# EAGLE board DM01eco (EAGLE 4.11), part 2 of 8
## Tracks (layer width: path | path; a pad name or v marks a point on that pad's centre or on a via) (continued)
-IM1  (via drill 0.61) (continued)
  Top 0.152: v356.24,75.57 356.24,69.22 347.35,60.32 347.35,57.78 D05.E2 | v346.07,222.25 346.07,226.69 353.06,233.68 v353.69,233.68 | v342.9,252.09 342.9,256.54 346.07,259.71 346.07,261.62 347.35,262.89 A05.E2
  Route2 0.152: v346.07,85.73 347.98,85.73 349.88,87.63 351.79,87.63 353.69,85.73 355.6,87.63 355.6,88.27 361.31,93.98 361.95,93.98 365.76,97.79 365.76,98.43 367.03,99.7 367.67,99.7 396.88,128.91 396.88,134.62 397.51,135.25 397.51,136.53 400.05,139.06 400.05,147.96 v403.23,151.13
  Route15 0.152: v356.24,75.57 356.24,76.2 346.71,85.73 v346.07,85.73
  Bottom 0.152: v403.23,151.13 404.5,152.4 387.35,169.55 387.35,170.81 386.71,171.45 386.71,173.36 388.62,175.26 364.49,199.39 364.49,200.03 363.22,201.3 362.58,201.3 358.77,205.11 358.77,206.38 352.43,212.72 352.43,215.9 v346.07,222.25 | v353.69,233.68 357.5,237.49 v342.9,252.09
-IM2  (via drill 0.61)
  Top 0.152: v358.77,58.42 351.79,51.43 347.98,51.43 D05.H2 | v374.65,144.78 374.65,145.41 375.92,146.69 375.92,147.96 387.35,159.39 387.35,160.02 398.14,170.81 398.78,170.81 400.05,172.09 400.05,172.72 v405.13,177.8
  Route2 0.152: v347.35,73.03 345.44,73.03 341.63,76.84 v342.9,78.11 | v334.64,90.81 334.64,92.08 346.07,103.51 346.07,109.86 374.65,138.43 v374.65,144.78
  Route15 0.152: v396.24,188.59 397.51,189.87 396.88,190.5 396.88,191.14 394.33,193.68 394.33,194.94 361.31,227.97 361.31,229.87 362.58,231.14 v361.95,231.78
  Bottom 0.152: v358.77,58.42 358.77,61.59 v347.35,73.03 | v342.9,78.11 336.55,84.46 336.55,85.09 333.38,88.27 333.38,89.54 v334.64,90.81 | v405.13,177.8 396.88,186.06 396.88,187.96 v396.24,188.59 | v361.95,231.78 361.95,232.41 360.68,233.68 360.68,234.95 346.07,249.56 346.07,255.27 347.35,256.54 A05.H2
-IM3  (via drill 0.61)
  Top 0.152: v374.65,61.59 374.65,62.23 381.63,69.22 381.63,69.85 v383.54,71.75 | v330.2,217.17 330.2,217.81 346.07,233.68 346.07,248.92 347.35,250.19 A05.K2
  Route2 0.152: v374.65,61.59 347.98,34.92 346.07,36.83 346.07,41.27 347.35,42.55 347.35,43.81 D05.K2 | v358.77,98.43 358.77,102.23 361.95,105.41 361.95,106.05 369.57,113.67 369.57,114.94 371.48,116.84 371.48,124.46 v372.11,125.09 | v330.2,184.15 330.2,183.52 332.11,181.61 336.55,186.06 336.55,189.87 335.28,191.14 343.54,199.39 343.54,201.93 342.26,203.2 344.81,205.74 344.81,208.91 333.38,220.34 v330.2,217.17
  Route15 0.152: v354.33,151.13 354.33,151.77 346.07,160.02 346.07,165.74 342.9,168.91 342.9,169.55 332.74,179.71 332.74,180.97 330.2,183.52 v330.2,184.15
  Bottom 0.152: v383.54,71.75 382.27,71.75 374.65,79.38 374.01,79.38 369.57,83.82 368.94,83.82 357.5,95.25 357.5,95.89 359.41,97.79 v358.77,98.43 | v372.11,125.09 372.11,125.73 371.48,126.37 371.48,131.44 365.12,137.8 365.12,139.06 361.95,142.24 361.95,143.51 v354.33,151.13
-IM4  (via drill 0.61)
  Top 0.152: v368.94,64.14 369.57,64.14 378.46,73.03 378.46,74.3 v387.99,83.82 | v386.08,159.39 v398.78,172.09 | v385.44,185.42 382.9,187.96 387.35,192.41 387.35,195.58 382.9,200.03 v386.71,203.84 | v354.33,247.65 353.69,247.65 351.79,245.75 348.62,245.75 347.98,245.11 A05.M2
  Route2 0.152: v368.94,64.14 368.94,62.87 351.79,45.72 351.15,45.72 346.71,41.27 347.35,40.64 347.35,38.73 D05.M2 | v368.3,110.49 367.67,111.12 370.2,113.67 370.2,114.94 372.75,117.48 372.75,118.11 374.65,120.02 374.65,123.19 373.38,124.46 384.18,135.25 384.18,140.34 v394.33,150.5
  Route15 0.152: v394.33,150.5 386.08,158.75 v386.08,159.39
  Bottom 0.152: v387.99,83.82 377.19,94.62 377.19,96.52 379.1,98.43 374.65,102.87 374.65,104.14 v368.3,110.49 | v398.78,172.09 398.14,172.09 386.71,183.52 386.71,184.15 v385.44,185.42 | v386.71,203.84 386.71,205.11 388.62,207.01 374.01,221.62 374.01,224.16 375.29,225.43 374.01,226.69 374.01,227.97 v354.33,247.65
-IM5  (via drill 0.61)
  Top 0.152: v361.95,50.16 361.95,49.53 347.98,35.56 347.98,32.38 D05.P2 | v331.47,83.82 332.11,83.82 336.55,88.27 336.55,90.81 335.28,92.08 340.36,97.16 345.44,97.16 350.52,102.23 v350.52,102.87
  Route2 0.152: v333.38,124.46 333.38,128.91 355.6,151.13 355.6,153.67 372.11,170.18 372.11,171.45 375.92,175.26 v375.92,175.9 | v355.6,195.58 355.6,198.12 370.2,212.72 370.2,220.34 371.48,221.62 371.48,229.87 366.39,234.95 361.95,230.5 359.41,230.5 353.69,236.22 352.43,236.22 349.25,239.4 347.98,238.12 A05.P2
  Bottom 0.152: v361.95,50.16 361.95,52.7 331.47,83.19 v331.47,83.82 | v350.52,102.87 349.88,102.87 335.92,116.84 335.92,119.38 337.19,120.65 v333.38,124.46 | v375.92,175.9 375.29,175.9 357.5,193.68 357.5,194.31 356.24,195.58 v355.6,195.58
-IM6  (via drill 0.61)
  Top 0.152: v393.06,78.74 387.35,73.03 387.35,68.58 341.63,22.86 343.54,20.95 345.44,20.95 347.35,22.86 347.35,24.77 D05.S2 | v392.43,87 393.06,87 403.23,97.16 403.86,97.16 v405.13,98.43 | v384.18,146.05 384.18,151.13 403.86,170.81 v403.86,171.45
  Route15 0.152: v405.13,98.43 396.88,106.68 396.88,118.75 393.06,122.56 393.06,125.09 394.97,127 387.35,134.62 387.35,135.89 384.18,139.06 v384.18,146.05 | v386.08,189.23 386.08,191.77 388.62,194.31 372.75,210.19 372.75,211.46 365.12,219.08 363.22,219.08 351.79,230.5 348.62,230.5 347.98,231.14 A05.S2
  Bottom 0.152: v393.06,78.74 393.06,86.36 v392.43,87 | v403.86,171.45 403.86,172.09 386.71,189.23 v386.08,189.23
-IM7  (via drill 0.61)
  Top 0.152: v385.44,65.41 384.81,65.41 344.81,25.4 344.81,22.86 D05.T2 | v366.39,106.05 367.67,106.05 374.65,113.03 374.65,113.67 376.56,115.57 377.19,115.57 378.46,116.84 378.46,117.48 379.73,118.75 380.37,118.75 400.05,138.43 v400.69,138.43
  Route2 0.152: v385.44,65.41 384.81,66.04 v393.7,74.93
  Route15 0.152: v386.08,170.18 386.08,172.72 388.62,175.26 371.48,192.41 371.48,198.75 346.07,224.16 346.07,226.69 344.81,227.97 A05.T2
  Bottom 0.152: v393.7,74.93 393.7,76.84 381,89.54 381,90.17 370.84,100.33 370.84,101.6 v366.39,106.05 | v400.69,138.43 400.69,149.86 375.92,174.62 379.1,177.8 383.54,173.36 383.54,172.72 v386.08,170.18
-IM8  (via drill 0.61)
  Top 0.152: v328.3,29.21 328.93,29.21 346.07,46.35 346.07,51.43 346.71,52.07 351.79,52.07 357.5,57.78 357.5,58.42 363.86,64.77 364.49,64.77 387.35,87.63 387.35,88.27 389.25,90.17 389.89,90.17 400.05,100.33 400.05,104.14 398.78,105.41 403.86,110.49 403.86,112.4 401.95,114.3 v403.23,115.57
  Route15 0.152: v392.43,135.89 392.43,136.53 389.89,139.06 389.89,142.24 372.11,160.02 372.11,160.66 371.48,161.29 371.48,173.36 364.49,180.34 364.49,181.61 369.57,186.69 368.3,187.96 368.3,188.59 358.14,198.75 358.14,200.03 353.69,204.47 353.06,204.47 351.79,205.74 351.79,212.72 353.69,214.63 349.25,219.08 347.35,219.08 344.81,221.62 A05.V2
  Bottom 0.152: v328.3,29.21 341,16.51 344.17,16.51 D05.V2 | v403.23,115.57 405.13,117.48 396.88,125.73 396.88,131.44 v392.43,135.89
-IM9  (via drill 0.61)
  Route2 0.152: v324.49,70.48 325.75,70.48 340.36,85.09 340.36,85.73 341.63,87 342.26,87 353.06,97.79 353.06,98.43 354.33,99.7 354.96,99.7 358.77,103.51 358.77,116.21 368.3,125.73 368.94,125.73 374.01,130.81 374.01,131.44 381.63,139.06 381.63,149.22 384.18,151.77 v384.18,154.94 | v372.11,189.23 372.11,189.87 384.18,201.93 v384.18,215.9
  Route15 0.152: v324.49,70.48 331.47,63.5 331.47,60.96 D06.D2 | v384.18,154.94 384.18,166.37 374.65,175.9 374.65,177.16 371.48,180.34 371.48,188.59 v372.11,189.23 | v384.18,215.9 384.18,217.17 354.96,246.38 354.33,246.38 352.43,248.28 352.43,248.92 336.55,264.8 333.38,264.8 332.11,266.06 A06.D2
-IM10  (via drill 0.61)
  Top 0.152: v217.17,96.52 217.81,96.52 222.25,100.97 222.25,103.51 220.98,104.78 229.24,113.03 v229.87,113.03
  Route2 0.152: v285.75,42.55 290.83,47.62 292.74,45.72 300.99,45.72 302.89,47.62 304.8,45.72 313.69,45.72 320.04,52.07 326.39,52.07 330.83,56.52 334.64,56.52 D06.E2 | v180.97,172.72 180.97,176.53 193.68,189.23 193.68,194.94 200.66,201.93 206.38,201.93 217.81,213.36 217.81,219.08 233.04,234.31 233.68,234.31 234.95,235.59 234.95,236.22 241.3,242.57 247.01,242.57 276.23,271.78 281.94,271.78 v295.27,285.11
  Route15 0.152: v285.75,42.55 285.75,45.09 281.94,48.89 276.23,48.89 262.89,62.23 257.81,62.23 255.27,64.77 254,64.77 247.65,71.12 242.57,71.12 227.97,85.73 227.33,85.73 217.17,95.89 v217.17,96.52 | v229.87,113.03 229.87,114.3 222.25,121.92 222.25,123.19 214,131.44 213.36,131.44 206.38,138.43 206.38,139.7 195.58,150.5 195.58,152.4 180.97,167 v180.97,172.72
  Bottom 0.152: v295.27,285.11 310.51,285.11 330.2,265.43 333.38,265.43 334.64,264.16 A06.E2
-IM11  (via drill 0.61)
  Top 0.152: v374.01,80.65 364.49,71.12 358.77,71.12 347.98,60.32 349.25,59.05 349.25,56.52 345.44,52.7 340.36,52.7 338.45,50.8 336.55,52.7 335.28,51.43 D06.H2 | v333.38,254 333.38,255.27 334.64,256.54 A06.H2
  Route2 0.152: v368.3,86.36 368.3,87.63 391.16,110.49 391.16,111.76 v391.8,112.4 | v363.22,154.31 363.22,155.58 384.18,176.53 384.18,180.34 380.37,184.15 v382.27,186.06
  Route15 0.152: v391.8,112.4 391.16,112.4 384.18,119.38 384.18,132.08 375.92,140.34 375.92,142.24 365.12,153.03 365.12,153.67 364.49,154.31 v363.22,154.31 | v382.27,186.06 382.27,187.96 377.19,193.04 377.19,194.94 379.1,196.85 367.67,208.28 364.49,208.28 363.86,208.91 362.58,208.91 358.77,212.72 358.77,215.27 358.14,215.9 358.14,218.44 346.07,230.5 346.07,236.22 342.26,240.03 341.63,240.03 340.36,241.3 340.36,242.57 333.38,249.56 v333.38,254
  Bottom 0.152: v374.01,80.65 373.38,80.65 369.57,84.46 368.94,84.46 368.3,85.09 v368.3,86.36
-INTERRUPT  (via drill 0.61)
  Top 0.152: v379.73,71.75 386.71,78.74 387.35,78.74 388.62,80.01 388.62,81.92 400.69,93.98 v401.32,93.98 | v400.05,95.89 398.14,97.79 v404.5,104.14 | v358.77,177.8 359.41,177.8 361.95,180.34 v361.95,180.97 | v354.33,191.14 v363.22,200.03 | v353.69,209.55 353.69,210.19 v359.41,215.9
  Route2 0.152: v379.73,71.75 378.46,71.75 372.11,65.41 365.76,65.41 365.12,64.77 363.86,64.77 357.5,58.42 357.5,57.78 338.45,38.73 335.28,38.73 D06.M2
  Route15 0.152: v341.63,236.22 340.36,236.22 335.92,240.66 335.92,243.21 335.28,243.84 A06.M2
  Bottom 0.152: v401.32,93.98 401.32,94.62 v400.05,95.89 | v404.5,104.14 404.5,104.78 387.99,121.29 387.35,121.29 386.08,122.56 386.08,124.46 384.18,126.37 384.18,139.7 381.63,142.24 381.63,149.86 373.38,158.12 373.38,158.75 361.31,170.81 361.31,171.45 358.77,173.99 v358.77,177.8 | v361.95,180.97 361.95,181.61 360.68,182.88 360.05,182.88 358.77,184.15 358.77,186.69 v354.33,191.14 | v363.22,200.03 v353.69,209.55 | v359.41,215.9 359.41,217.17 342.9,233.68 342.9,234.95 v341.63,236.22
-SKIP  (via drill 0.61)
  Top 0.152: v348.62,191.77 v352.43,195.58
  Route2 0.152: v316.87,53.34 316.87,55.24 332.11,70.48 333.38,70.48 344.81,81.92 346.07,81.92 346.71,82.55 351.15,82.55 356.24,87.63 356.24,88.27 361.31,93.34 361.95,93.34 365.76,97.16 367.03,97.16 368.3,98.43 368.3,99.7 383.54,114.94 v384.18,114.94 | v381,128.91 381,130.81 v385.44,135.25 | v352.43,195.58 358.77,201.93 358.77,215.27 356.87,217.17 356.87,219.71 358.77,221.62 358.77,223.52 351.15,231.14 349.88,231.14 349.25,230.5 346.07,230.5 344.17,232.41 v347.98,236.22
  Route15 0.152: v385.44,135.25 385.44,137.16 383.54,139.06 383.54,140.34 381.63,142.24 381.63,144.15 371.48,154.31 371.48,160.66 364.49,167.64 364.49,169.55 366.39,171.45 364.49,173.36 363.86,173.36 361.31,175.9 361.31,177.16 348.62,189.87 v348.62,191.77
  Bottom 0.152: v316.87,53.34 318.77,51.43 317.5,50.16 317.5,46.99 321.31,43.18 326.39,43.18 328.3,41.27 330.83,43.81 334.64,43.81 D06.K2 | v384.18,114.94 384.18,125.73 v381,128.91 | v347.98,236.22 349.88,238.12 342.9,245.11 342.9,245.75 339.09,249.56 335.92,249.56 335.28,250.19 A06.K2
ADD_ACC  (via drill 0.61)
  Top 0.152: B31.S2 17.78,162.56 17.78,165.74 26.04,173.99 26.04,176.53 26.67,177.16 B30.L2 27.3,178.44 28.57,179.71 28.57,181.61 29.84,182.88 v30.48,182.88 | v109.86,194.94 109.22,194.31 111.76,191.77 113.67,191.77 114.94,193.04 118.75,193.04 B23.E2 | v309.25,247.02 306.7,244.47 311.15,240.03 311.15,237.49 309.88,236.22 309.88,232.41 A08.S2 | v262.25,290.83 240.66,290.83 231.14,281.3 v226.69,281.3 | v184.15,256.54 184.15,255.91 148.59,220.34 143.51,220.34 127,203.84 127,201.3 128.27,200.03 121.28,193.04 v121.28,192.41
  Route2 0.152: v109.86,194.94 109.86,194.31 97.79,182.25 92.71,182.25 88.9,178.44 88.9,175.9 90.17,174.62 85.09,169.55 79.38,169.55 60.33,150.5 55.88,150.5 v50.16,144.78 | v226.69,281.3 219.07,281.3 217.81,280.03 212.09,280.03 209.55,277.5 206.38,277.5 187.32,258.44 186.06,258.44 v184.15,256.54
  Route15 0.152: B30.S2 29.84,162.56 29.84,166.37 28.57,167.64 28.57,175.9 27.3,177.16 B30.L2 | v309.25,247.02 313.06,250.83 279.4,284.48 271.78,284.48 267.97,288.29 264.8,288.29 v262.25,290.83
  Bottom 0.152: B32.H2 5.08,186.69 5.08,184.15 10.16,179.07 13.34,179.07 13.97,178.44 B31.L2 13.97,177.16 13.97,173.99 8.26,168.28 12.7,163.83 15.88,163.83 17.14,162.56 B31.S2 | 28.57,191.77 29.21,191.77 30.48,193.04 B30.E2 | 28.57,191.77 22.86,191.77 21.59,193.04 17.78,193.04 B31.E2 | v50.16,144.78 49.53,144.78 40.64,153.67 35.56,153.67 31.11,158.12 31.11,160.66 30.48,161.29 B30.S2 | v121.28,192.41 120.02,192.41 119.38,193.04 B23.E2 | 28.57,191.77 28.57,184.78 v30.48,182.88
ADD_ACC0  (via drill 0.61)
  Top 0.152: v200.66,34.92 200.66,35.56 198.12,38.1 v194.94,34.92 | v126.36,92.08 130.18,95.89 130.18,97.16 147.96,114.94 v147.96,115.57
  Route15 0.152: v200.66,34.92 201.29,34.92 205.1,31.12 206.38,31.12 207.65,29.84 207.01,29.21 208.28,27.94 208.91,27.94 213.36,23.5 214,23.5 221.62,15.88 221.62,15.24 228.6,8.26 239.4,8.26 240.03,7.62 286.38,7.62 287.65,6.35 306.07,24.77 309.25,24.77 D08.S2 | v105.41,149.86 102.87,149.86 97.79,154.94 97.79,155.58 96.52,156.84 95.89,156.84 79.38,173.36 79.38,179.07 71.12,187.33 68.58,187.33 B27.H2
  Bottom 0.152: v194.94,34.92 186.69,43.18 181.61,43.18 175.9,48.89 175.26,48.89 168.28,55.88 168.28,61.59 154.94,74.93 154.31,74.93 142.24,87 139.7,87 139.06,86.36 139.7,85.73 139.7,85.09 135.89,81.28 132.08,85.09 132.08,86.36 v126.36,92.08 | v147.96,115.57 146.05,115.57 123.19,138.43 116.84,138.43 v105.41,149.86
ADD_ACC1  (via drill 0.61)
  Top 0.152: v73.03,10.79 108.58,10.79 114.94,17.14 117.47,17.14 118.11,16.51 v117.47,15.88
  Route2 0.152: v73.03,10.79 53.98,29.84 51.44,29.84 49.53,27.94 21.59,55.88 19.05,55.88 17.78,54.61 15.88,56.52 15.88,90.17 28.57,102.87 28.57,127.64 29.21,128.27 29.21,129.54 50.8,151.13 50.8,153.03 52.7,154.94 52.7,156.21 64.77,168.28 64.77,170.81 B27.N2 | v154.94,1.27 156.84,3.18 161.93,3.18 163.19,4.45 188.59,4.45 189.87,5.71 215.9,5.71 217.17,6.99 222.88,6.99 223.52,7.62 225.43,7.62 241.3,23.5 244.47,23.5 245.75,24.77 D13.S2
  Route15 0.152: v117.47,15.88 119.38,15.88 121.28,13.97 124.46,13.97 126.36,12.07 128.27,12.07 132.08,8.26 143.51,8.26 145.41,6.35 148.59,6.35 151.76,3.18 153.03,3.18 v154.94,1.27
ADD_ACC2  (via drill 0.61)
  Top 0.152: v132.72,92.08 132.72,90.17 133.99,88.9 v128.91,83.82
  Route15 0.152: v83.19,149.22 83.19,140.97 99.06,125.09 104.14,125.09 v109.86,119.38 | v128.91,83.82 129.54,83.82 136.53,76.84 136.53,74.93 166.37,45.09 166.37,43.81 168.28,41.91 168.28,36.83 177.8,27.3 179.71,27.3 182.25,24.77 D18.S2
  Bottom 0.152: v83.19,149.22 78.74,153.67 73.66,153.67 72.39,154.94 68.58,154.94 B27.U2 | v109.86,119.38 111.12,119.38 125.09,105.41 125.73,105.41 128.91,102.23 128.91,100.33 133.35,95.89 133.35,92.71 v132.72,92.08
ADD_ACC3  (via drill 0.61)
  Route2 0.152: v18.41,130.81 24.13,136.53 21.59,139.06 21.59,142.88 31.75,153.03 31.75,154.31 41.27,163.83 41.27,169.55 48.26,176.53 48.26,177.8 49.53,179.07 50.16,179.07 55.24,184.15 55.24,186.69 B28.H2
  Route15 0.152: v18.41,130.81 18.41,128.91 79.38,67.95 79.38,56.52 80.01,55.88 85.09,55.88 111.12,29.84 112.39,29.84 114.94,27.3 116.84,27.3 118.75,25.4 D23.S2
ADD_ACC4  (via drill 0.61)
  Top 0.152: v67.94,34.92 59.05,26.04 55.88,26.04 D28.S2 | v4.45,104.78 38.73,139.06 38.73,140.97 v53.98,156.21
  Bottom 0.152: v67.94,34.92 67.94,36.2 66.67,37.47 66.67,42.55 v4.45,104.78 | v53.98,156.21 53.98,169.55 52.7,170.81 B28.N2
ADD_ACC5  (via drill 0.61)
  Top 0.152: v76.83,200.66 74.93,202.56 92.08,219.71 97.16,219.71 104.78,227.33 104.78,229.87 106.05,231.14 A24.S2
  Route2 0.152: v45.72,169.55 46.99,169.55 71.12,193.68 71.75,193.04 73.03,194.31 73.03,195.58 76.83,199.39 v76.83,200.66
  Bottom 0.152: v45.72,169.55 45.72,168.91 52.07,162.56 50.8,161.29 50.8,158.12 53.98,154.94 55.24,154.94 B28.U2
ADD_ACC6
  Route15 0.152: B29.H2 42.55,187.96 42.55,191.77 41.27,193.04 41.27,197.49 40.64,198.12 40.64,199.39 34.29,205.74 34.29,219.08 40.64,225.43 38.1,227.97 38.1,229.24 41.91,233.05 42.55,232.41 A29.S2
B32M  (via drill 0.61)
  Top 0.152: PDP-12/8I/8.2 12.06,286.38 10.79,286.38 PDP-12/8I/8.4 9.53,286.38 8.26,286.38 PDP-12/8I/8.6 7.62,285.75 3.17,281.3 3.17,221.62 1.91,220.34 v1.91,215.27
  Route15 0.152: v1.91,215.27 2.54,214.63 2.54,205.11 7.62,200.03 2.54,194.94 2.54,192.41 3.17,191.77 3.17,180.34 4.45,179.07 4.45,175.26 B32.M2
B_ENABLE0  (via drill 0.61)
  Top 0.152: v347.98,183.52 347.98,184.15 353.69,189.87 354.33,189.87 356.24,191.77 358.77,191.77 360.05,193.04 B04.E2 | v231.14,282.57 227.97,285.75 214,271.78 213.36,271.78 v206.38,264.8 | v338.45,200.66 335.28,197.49 335.28,194.31 B06.E2
  Route2 0.152: A20.S2 157.48,232.41 160.66,232.41 183.51,255.27 184.15,255.27 184.78,255.91 186.69,255.91 189.23,253.37 196.85,260.99 196.85,261.62 200.66,265.43 203.84,265.43 204.47,266.06 A16.D2
  Route15 0.152: v338.45,200.66 337.82,200.66 333.38,205.11 333.38,207.01 332.11,208.28 330.83,208.28 325.12,214 323.85,214 323.21,214.63 318.77,214.63 314.32,219.08 v313.06,219.08
  Bottom 0.152: B14.T2 229.87,159.39 229.87,162.56 218.44,173.99 218.44,174.62 214,179.07 213.36,179.07 193.68,198.75 193.68,204.47 189.87,208.28 187.96,208.28 182.88,213.36 179.07,213.36 168.91,223.52 168.28,223.52 161.29,230.5 158.12,230.5 157.48,231.14 A20.S2 | v347.98,183.52 338.45,193.04 335.28,193.04 B06.E2 | v231.14,282.57 233.04,280.67 237.49,280.67 239.4,278.76 241.3,278.76 242.57,277.5 247.65,277.5 258.44,266.7 258.44,264.16 A12.E2 259.08,262.89 259.71,262.25 259.71,259.71 267.33,252.09 273.05,252.09 277.5,247.65 278.76,247.65 283.21,243.21 288.29,243.21 312.42,219.08 v313.06,219.08 | v206.38,264.8 205.1,266.06 A16.D2
B_ENABLE1  (via drill 0.61)
  Top 0.152: 340.36,189.23 346.07,194.94 v350.52,194.94 | 340.36,189.23 332.11,180.97 332.11,178.44 B06.L2 | v247.65,250.83 248.28,251.46 250.19,251.46 251.46,252.73 256.54,252.73 258.44,254.64 258.44,256.54 A12.H2 | v216.53,257.81 216.53,256.54 212.09,252.09 208.91,252.09 208.28,251.46 A16.K2 | v341,189.23 340.36,189.23
  Route2 0.152: v191.13,269.24 168.28,246.38 162.56,246.38 157.48,241.3 157.48,238.76 A20.P2
  Route15 0.152: v350.52,194.94 350.52,193.68 354.33,189.87 355.6,189.87 356.24,189.23 358.77,189.23 360.05,187.96 B04.H2 | v191.13,269.24 191.77,269.88 206.38,255.27 206.38,252.73 207.65,251.46 A16.K2 | v197.49,168.91 204.47,161.93 204.47,159.39 B16.T2 | v179.71,194.94 182.25,197.49 173.99,205.74 173.99,214.63 172.09,216.53 172.09,217.81 170.81,219.08 170.81,221.62 158.12,234.31 158.12,236.86 157.48,237.49 A20.P2 | v247.65,250.83 247.65,252.09 240.66,259.08 238.12,259.08 224.16,245.11 223.52,245.75 222.88,245.75 222.25,246.38 221.62,246.38 220.34,247.65 223.52,250.83 v216.53,257.81 | v341,189.23 341,191.14 333.38,198.75 333.38,203.84 330.2,207.01 330.2,207.65 329.56,208.28 325.12,208.28 321.31,212.09 317.5,208.28 v311.79,208.28 | v274.32,245.75 273.05,245.75 262.89,255.91 259.71,255.91 259.08,256.54 A12.H2
  Bottom 0.152: v197.49,168.91 196.85,168.91 194.94,170.81 194.94,172.72 188.59,179.07 187.96,179.07 180.97,186.06 180.97,193.68 v179.71,194.94 | v311.79,208.28 311.15,208.28 281.31,238.12 281.31,238.76 277.5,242.57 276.86,242.57 274.32,245.11 v274.32,245.75
B_ENABLE2  (via drill 0.61)
  Top 0.152: v189.23,170.18 189.23,170.81 188.59,171.45 224.79,207.65 v225.43,207.65 | v178.44,225.43 182.25,221.62 187.96,227.33 193.68,227.33 198.75,232.41 199.39,232.41 200.66,233.68 203.84,233.68 204.47,234.31 A16.R2 | v248.28,258.44 244.47,258.44 v211.46,225.43 | v300.36,150.5 297.81,150.5 v289.56,142.24 | v254,171.45 252.73,171.45 245.11,163.83 244.47,163.83 231.78,151.13 229.24,151.13 226.06,147.96 v223.52,147.96
  Route2 0.152: B04.K2 360.05,180.34 360.05,177.8 348.62,166.37 342.9,166.37 339.09,162.56 335.28,162.56 B06.S2 334.64,161.29 334.64,158.75 326.39,150.5 324.49,150.5 v315.6,141.61 | v194.94,163.83 192.41,161.29 192.41,159.39 B17.T2 | v223.52,147.96 218.44,142.88 214.63,142.88 v210.19,138.43
  Route15 0.152: v248.28,258.44 251.46,255.27 252.09,255.27 255.91,251.46 258.44,251.46 A12.K2
  Bottom 0.152: v194.94,163.83 194.94,165.1 189.87,170.18 v189.23,170.18 | v225.43,207.65 225.43,209.55 224.16,210.82 224.16,212.72 v211.46,225.43 206.38,230.5 206.38,233.05 205.1,234.31 A16.R2 | v178.44,225.43 178.44,226.06 160.66,243.84 157.48,243.84 A20.M2 | v315.6,141.61 310.51,141.61 309.25,142.88 307.98,142.88 v300.36,150.5 | v289.56,142.24 288.29,142.24 276.23,154.31 270.51,154.31 269.88,154.94 269.88,159.39 269.24,160.02 264.16,160.02 257.81,166.37 257.81,167 254,170.81 v254,171.45 | v210.19,138.43 207.01,138.43 205.1,140.34 205.1,140.97 200.03,146.05 200.03,147.32 195.58,151.77 195.58,153.67 197.49,155.58 196.22,156.84 193.68,156.84 192.41,158.12 B17.T2
B_ENABLE3  (via drill 0.61)
  Top 0.152: v166.37,245.11 167,245.11 189.87,267.97 191.13,267.97 191.77,267.33 A17.D2 | 238.76,227.33 254,242.57 257.18,242.57 258.44,243.84 A12.M2 | 238.76,227.33 205.74,194.31 205.1,194.31 185.42,174.62 187.96,172.09 187.96,170.81 186.69,169.55 186.69,168.28 185.42,167 184.78,167 179.71,161.93 179.71,159.39 B18.T2 | 238.76,227.33 v239.4,227.33
  Route2 0.152: v340.36,158.75 341,158.75 343.54,161.29 343.54,162.56 344.81,163.83 346.71,163.83 355.6,172.72 358.77,172.72 360.05,173.99 B04.M2 | v305.44,186.69 306.07,187.33 304.8,188.59 304.8,191.77 306.7,193.68 309.25,193.68 B08.E2
  Route15 0.152: v340.36,158.75 340.36,159.39 307.98,191.77 309.25,193.04 B08.E2 | v305.44,186.69 303.53,184.78 302.89,185.42 302.26,185.42 295.27,192.41 295.27,198.75 287.02,207.01 287.02,219.08 275.59,230.5 269.88,230.5 259.71,240.66 259.71,243.21 259.08,243.84 A12.M2
  Bottom 0.152: v166.37,245.11 156.84,254.64 155.57,253.37 156.84,252.09 156.84,251.46 A20.K2 | v239.4,227.33 238.76,227.97 238.76,229.24 206.38,261.62 200.66,261.62 196.22,266.06 192.41,266.06 A17.D2
B_ENABLE4  (via drill 0.61)
  Top 0.152: v193.04,186.69 191.77,185.42 190.5,185.42 184.15,179.07 184.15,178.44 176.53,170.81 175.9,170.81 167,161.93 167,159.39 B19.T2 | v173.35,216.53 173.35,219.08 167,225.43 v179.07,237.49 190.5,248.92 193.68,248.92 194.94,250.19 A17.K2 | 327.02,195.58 309.88,178.44 306.7,178.44 B08.L2 | 327.02,195.58 329.56,195.58 v330.2,196.22 | v264.8,246.38 264.16,246.38 260.35,242.57 260.35,241.94 259.08,240.66 259.08,238.76 A12.P2 | v323.85,198.75 326.39,198.75 328.3,196.85 327.02,195.58 | v208.91,240.03 208.91,241.94 215.9,248.92 220.34,248.92 v221.62,247.65
  Route15 0.152: v193.04,186.69 186.69,193.04 186.69,194.31 189.23,196.85 180.97,205.11 180.97,208.91 v173.35,216.53 | v342.9,183.52 349.25,177.16 349.25,176.53 355.6,170.18 358.77,170.18 360.05,168.91 B04.P2 | v264.8,246.38 266.7,246.38 276.86,236.22 282.57,236.22 314.32,204.47 315.6,204.47 321.31,198.75 v323.85,198.75 | v221.62,247.65 221.62,248.28 231.14,257.81 v230.5,258.44
  Bottom 0.152: v179.07,237.49 179.07,238.12 160.66,256.54 157.48,256.54 A20.H2 | v330.2,196.22 330.2,195.58 342.26,183.52 v342.9,183.52 | v208.91,240.03 198.75,250.19 195.58,250.19 A17.K2 | v230.5,258.44 234.95,258.44 250.82,242.57 256.54,242.57 257.18,241.94 257.18,240.03 258.44,238.76 A12.P2
B_ENABLE5  (via drill 0.61)
  Top 0.152: v330.2,185.42 328.93,184.15 | 328.93,184.15 309.88,165.1 309.88,162.56 B08.S2 | v195.58,227.97 193.68,226.06 193.68,225.43 192.41,224.16 191.77,224.16 177.16,209.55 184.15,202.56 184.15,199.39 180.97,196.22 180.97,189.23 164.47,172.72 163.83,172.72 162.56,171.45 162.56,170.81 154.31,162.56 154.31,159.39 B20.T2 | v217.81,205.11 221.62,205.11 225.43,208.91 226.06,208.91 243.84,226.69 250.19,226.69 254.63,231.14 258.44,231.14 A12.S2 | 328.93,184.15 325.75,187.33 330.2,191.77 330.2,193.04 336.55,199.39 336.55,200.66 334.01,203.2 332.74,201.93 330.83,201.93 328.93,203.84 330.83,205.74 330.83,211.46 v331.47,212.09 | v278.76,248.92 276.86,248.92 274.95,250.83 269.88,245.75 v269.88,238.76
  Route2 0.152: v269.88,238.76 269.24,238.76 262.89,232.41 262.89,230.5 264.8,228.6 262.89,226.69 260.99,226.69 257.81,229.87 259.08,231.14 A12.S2
  Route15 0.152: v330.2,185.42 334.01,185.42 355.6,163.83 358.77,163.83 360.05,162.56 B04.S2 | A20.E2 157.48,262.89 160.66,262.89 184.15,239.4 185.42,239.4 187.32,237.49 187.32,236.86 187.96,236.22 191.13,236.22 191.77,235.59 A17.R2 | v331.47,212.09 330.2,212.09 327.02,215.27 327.02,216.53 320.04,223.52 314.32,223.52 313.69,224.16 307.34,224.16 300.99,230.5 295.27,230.5 282.57,243.21 282.57,248.28 281.94,248.92 v278.76,248.92
  Bottom 0.152: A17.R2 192.41,234.31 193.68,233.05 193.68,231.14 195.58,229.24 v195.58,227.97 203.2,220.34 207.01,220.34 208.91,218.44 206.38,215.9 206.38,212.72 210.82,208.28 215.26,208.28 217.81,205.74 v217.81,205.11
B_ENABLE6  (via drill 0.61)
  Top 0.152: B23.S2 119.38,162.56 119.38,165.1 124.46,170.18 125.73,170.18 v127,171.45 127,172.09 v132.72,177.8 | A18.D2 179.07,266.06 178.44,265.43 178.44,262.89 172.72,257.18 170.81,259.08 v169.54,259.08 168.91,259.08 146.05,236.22 146.05,235.59 137.79,227.33 137.16,227.33 124.46,214.63 120.02,214.63 115.57,210.19 115.57,207.65 120.65,202.56 120.65,199.39 115.57,194.31 v114.94,194.31 | v220.34,246.38 v214.63,246.38 | v299.08,251.46 296.55,254 275.59,233.05 273.69,233.05 v273.05,232.41 | v269.88,235.59 268.61,236.86 267.97,236.22 267.33,236.22 266.7,235.59 266.7,233.05 267.97,231.78 262.89,226.69 259.71,226.69 259.08,226.06 A12.U2
  Route15 0.152: v169.54,259.08 165.1,259.08 158.12,266.06 154.31,266.06 A20.D2 | v220.34,246.38 220.98,245.75 222.25,245.75 231.14,236.86 237.49,236.86 241.3,233.05 247.01,233.05 248.28,231.78 249.56,231.78 255.27,226.06 258.44,226.06 A12.U2 | v214.63,246.38 214.63,247.02 212.09,249.56 203.84,249.56 201.93,247.65 183.51,266.06 179.71,266.06 A18.D2 | v368.3,153.03 367.67,153.67 365.76,153.67 363.86,155.58 360.68,155.58 B04.U2 | v369.57,156.84 368.3,158.12 368.3,160.66 369.57,161.93 361.95,169.55 361.95,170.81 355.6,177.16 355.6,179.71 356.87,180.97 347.98,189.87 347.98,191.14 346.07,193.04 346.07,194.94 350.52,199.39 347.98,201.93 347.98,203.2 314.32,236.86 313.69,236.86 v299.08,251.46
  Bottom 0.152: v127,171.45 127,170.18 137.16,160.02 140.34,160.02 140.97,159.39 B21.T2 | v368.3,153.03 370.84,155.58 v369.57,156.84 | v273.05,232.41 v269.88,235.59 | v132.72,177.8 131.44,177.8 v114.94,194.31
BMPX0  (via drill 0.61)
  Top 0.152: v323.21,48.26 309.88,34.92 309.88,32.38 D08.P2 | v302.89,73.66 v307.34,78.11 | v267.33,127.64 268.61,127.64 v283.85,142.88 | v277.5,151.77 277.5,152.4 295.27,170.18 295.27,172.72 296.55,173.99 B09.M2
  Bottom 0.152: v323.21,48.26 325.75,50.8 v302.89,73.66 | v307.34,78.11 307.34,80.65 301.62,86.36 301.62,87 271.14,117.48 270.51,117.48 269.24,118.75 269.24,122.56 270.51,123.83 267.33,127 v267.33,127.64 | v283.85,142.88 283.85,144.15 280.67,147.32 280.67,148.59 v277.5,151.77 | B10.D2 281.31,196.22 281.31,193.04 292.74,181.61 292.74,179.07 291.46,177.8 292.74,176.53 294.64,176.53 296.55,174.62 B09.M2
BMPX1  (via drill 0.61)
  Top 0.152: v287.02,69.85 249.56,32.38 246.38,32.38 D13.P2 | v242.57,113.67 242.57,114.3 257.18,128.91 257.18,129.54 262.25,134.62 262.89,134.62 278.76,150.5 278.76,153.03 295.91,170.18 295.91,171.45 298.45,173.99 298.45,175.9 297.18,177.16 295.27,175.26 295.27,173.36 294,172.09 B09.N2
  Route15 0.152: B10.F2 281.31,189.87 281.31,186.06 284.48,182.88 285.75,182.88 299.72,168.91 299.72,168.28 297.18,165.74 295.27,167.64 295.27,169.55 294,170.81 B09.N2
  Bottom 0.152: v287.02,69.85 259.71,97.16 259.08,97.16 254,102.23 254,102.87 246.38,110.49 245.75,110.49 v242.57,113.67
BMPX2  (via drill 0.61)
  Top 0.152: v307.34,155.58 304.8,153.03 304.8,152.4 292.74,140.34 292.74,139.06 261.62,107.95 260.99,107.95 257.81,104.78 257.81,104.14 253.37,99.7 252.73,99.7 251.46,98.43 251.46,97.79 240.66,87 240.03,87 238.76,85.73 238.76,85.09 186.06,32.38 182.88,32.38 D18.P2
  Route15 0.152: B10.J2 281.31,183.52 282.57,183.52 283.85,182.25 285.75,182.25 295.27,172.72 295.27,170.18 296.55,168.91 B09.P2
  Bottom 0.152: v307.34,155.58 306.7,155.58 297.81,164.47 297.81,167 297.18,167.64 B09.P2
BMPX3  (via drill 0.61)
  Top 0.152: v274.32,180.97 242.57,149.22 241.3,149.22 233.04,140.97 231.78,140.97 215.9,125.09 214.63,125.09 213.36,123.83 213.36,123.19 189.87,99.7 189.23,99.7 187.96,98.43 187.96,97.79 122.56,32.38 119.38,32.38 D23.P2 | v290.83,163.83 291.46,164.47 293.37,164.47 B09.R2
  Bottom 0.152: v274.32,180.97 279.4,175.9 | 279.4,175.9 280.67,177.16 B10.L2 | v290.83,163.83 290.83,164.47 279.4,175.9
BMPX4  (via drill 0.61)
  Top 0.152: v99.69,73.03 59.05,32.38 55.88,32.38 D28.P2 | v132.72,41.27 132.72,41.91 162.56,71.75 165.1,71.75 175.9,82.55 178.44,82.55 186.06,90.17 186.69,90.17 213.36,116.84 213.36,117.48 214.63,118.75 215.26,118.75 v229.24,132.72 | v233.04,129.54 244.47,140.97 247.65,140.97 276.86,170.18 280.04,170.18 280.67,170.81 B10.N2
  Route2 0.152: B09.S2 296.55,161.29 294.64,161.29 294,160.66 292.1,160.66 291.46,160.02 289.56,160.02 281.31,168.28 281.31,170.81 B10.N2
  Route15 0.152: v229.24,132.72 229.87,132.72 v233.04,129.54
  Bottom 0.152: v99.69,73.03 123.83,48.89 125.09,48.89 v132.72,41.27
BMPX5  (via drill 0.61)
  Route2 0.152: B09.T2 293.37,159.39 289.56,159.39 282.57,166.37 281.31,165.1 B10.R2 280.67,164.47 280.04,163.83 276.23,163.83 272.42,160.02 266.7,160.02 251.46,144.78 248.92,147.32 248.92,147.96 252.09,151.13 252.09,151.77 255.27,154.94 254,156.21 v254,158.75 | v137.79,278.13 137.16,278.13 120.65,261.62 120.65,260.99 117.47,257.81 117.47,252.73 106.68,241.94 106.68,238.76 A24.P2
  Route15 0.152: v137.79,278.13 139.7,278.13 165.1,252.73 165.1,251.46 168.28,248.28 168.28,243.21 187.96,223.52 193.04,223.52 198.75,217.81 200.03,217.81 231.78,186.06 237.49,186.06 238.76,184.78 238.76,183.52 236.22,180.97 254.63,162.56 254.63,160.66 253.37,159.39 v254,158.75
BMPX6  (via drill 0.61)
  Top 0.152: v81.92,274.32 46.35,238.76 43.18,238.76 A29.P2 | v210.19,219.08 v220.98,219.08
  Bottom 0.152: v81.92,274.32 98.42,290.83 122.56,290.83 123.83,289.56 135.25,289.56 140.97,283.84 146.05,283.84 210.19,219.71 v210.19,219.08 | v220.98,219.08 227.97,219.08 231.14,215.9 233.04,215.9 244.47,204.47 244.47,198.12 280.04,162.56 | 280.04,162.56 280.04,160.02 280.67,159.39 B10.T2 | 280.04,162.56 289.56,153.03 293.37,153.03 B09.V2
BREAK  (via drill 0.61)
  Top 0.152: 306.07,179.07 307.98,179.07 309.25,180.34 B08.K2 | 306.07,179.07 305.44,179.07 304.17,177.8 307.98,173.99 307.98,170.81 306.7,169.55 306.7,165.74 B08.R2 | 306.07,179.07 306.7,179.71 304.8,181.61 304.8,184.78 309.88,189.87 v309.88,191.77 311.79,193.68 310.51,194.94 310.51,197.49 v328.3,215.27 | v308.61,233.68 309.25,234.31 309.25,237.49 A08.P2 | 327.02,176.53 332.74,176.53 334.64,178.44 334.64,180.34 B06.K2 | v319.4,168.91 327.02,176.53 | v338.45,188.59 338.45,187.96 327.02,176.53 | v109.86,173.99 109.86,174.62 142.88,207.65 144.15,207.65 149.22,212.72 149.22,220.34 177.8,248.92 180.97,248.92 182.25,250.19 A18.K2 182.88,251.46 183.51,252.09 183.51,254.64 191.13,262.25 196.22,262.25 198.12,264.16 199.39,264.16 200.66,265.43 201.29,265.43 209.55,273.69 209.55,277.5 v215.9,283.84
  Route2 0.152: v327.66,160.02 329.56,160.02 331.47,161.93 331.47,164.47 B06.R2
  Route15 0.152: v338.45,188.59 337.19,188.59 332.11,193.68 332.11,196.22 B06.D2 | v109.86,173.99 115.57,168.28 115.57,165.74 B23.R2 | v308.61,233.68 304.17,233.68 300.99,236.86 295.27,236.86 263.52,268.6 256.54,268.6 247.65,277.5 246.38,277.5 239.4,284.48 216.53,284.48 v215.9,283.84
  Bottom 0.152: 318.77,168.91 310.51,177.16 310.51,179.71 309.88,180.34 B08.K2 | 318.77,168.91 v327.66,160.02 | v309.88,191.77 309.25,191.77 306.7,194.31 306.7,196.22 B08.D2 | v308.61,233.68 310.51,233.68 328.3,215.9 v328.3,215.27 | 318.77,168.91 v319.4,168.91 | A19.D2 167,266.06 170.18,266.06 180.97,255.27 180.97,252.73 182.25,251.46 A18.K2
BREAK\  (via drill 0.61)
  Top 0.152: v360.05,171.45 v334.64,146.05 | v220.98,266.06 217.17,269.88 186.69,239.4 183.51,239.4 182.88,238.76 A18.P2
  Route2 0.152: v374.65,155.58 375.29,156.21 373.38,158.12 373.38,161.29 B03.S2
  Bottom 0.152: v374.65,155.58 374.65,156.21 368.3,162.56 368.3,163.19 v360.05,171.45 | v334.64,146.05 278.76,201.93 276.86,201.93 274.95,200.03 272.42,202.56 272.42,205.11 273.69,206.38 273.05,207.01 273.05,214 v220.98,266.06 | A18.N2 179.71,240.66 180.34,240.66 182.25,238.76 A18.P2
BRK_REQ  (via drill 0.61)
  Top 0.152: v240.03,282.57 249.56,282.57 v255.91,288.92
  Route2 0.152: v192.41,290.19 190.5,288.29 173.99,288.29 173.35,287.65 158.75,287.65 158.12,287.02 156.84,287.02 153.03,290.83 140.97,290.83 139.06,288.92 129.54,288.92 121.92,281.3 113.67,281.3 113.03,280.67 99.69,280.67 96.52,277.5 92.71,277.5 87,271.78 85.72,271.78 72.39,258.44 66.67,258.44 31.75,223.52 26.04,223.52 13.34,210.82 13.34,205.74 5.08,197.49 1.91,197.49 B32.D2
  Route15 0.152: v192.41,290.19 193.68,288.92 201.93,288.92 203.2,287.65 206.38,287.65 212.72,281.3 216.53,281.3 219.07,283.84 238.76,283.84 v240.03,282.57 | v255.91,288.92 263.52,288.92 264.8,287.65 267.97,287.65 271.78,283.84 279.4,283.84 307.98,255.27 307.98,252.73 309.25,251.46 A08.K2
BRK_REQ0  (via drill 0.61)
  Top 0.152: 231.78,178.44 233.68,178.44 238.76,183.52 238.76,184.15 240.03,185.42 241.3,185.42 244.47,188.59 250.19,188.59 254,192.41 255.91,192.41 v256.54,193.04 | 231.78,178.44 230.5,178.44 B14.L2 | v150.5,208.28 149.22,208.28 122.56,181.61 119.38,181.61 B23.K2 | v163.19,203.2 164.47,203.2 172.09,210.82 173.99,210.82 v181.61,218.44 | 231.78,178.44 v231.78,182.88 | v354.33,217.17 351.15,217.17 347.35,220.98 v337.82,211.46 | v304.17,196.85 302.89,196.85 300.99,194.94 295.27,194.94 294,196.22 B09.D2
  Route2 0.152: v271.14,179.07 273.05,179.07 273.69,179.71 274.32,179.71 275.59,180.97 275.59,182.25 290.19,196.85 293.37,196.85 B09.D2 | v205.1,144.15 206.38,144.15 215.9,153.67 215.9,154.94 222.25,161.29 222.25,163.83 220.98,165.1 226.06,170.18 231.14,170.18 231.78,170.81 231.78,175.9 230.5,177.16 B14.L2 | v329.56,219.08 329.56,218.44 323.85,212.72 323.85,211.46 313.69,201.3 308.61,201.3 v304.17,196.85
  Route15 0.152: v181.61,218.44 181.61,217.81 194.31,205.11 199.39,205.11 203.2,201.3 204.47,201.3 207.01,198.75 212.09,198.75 224.16,186.69 224.79,186.69 228.6,182.88 v231.78,182.88
  Bottom 0.152: v256.54,193.04 260.99,188.59 261.62,188.59 263.52,186.69 263.52,186.06 264.16,185.42 269.24,185.42 269.88,184.78 269.88,180.34 v271.14,179.07 | v150.5,208.28 151.76,208.28 158.75,201.3 161.29,201.3 v163.19,203.2 | v205.1,144.15 205.74,144.15 211.46,138.43 212.72,138.43 226.06,125.09 226.06,123.83 227.33,122.56 227.97,122.56 250.82,99.7 250.82,99.06 252.73,97.16 253.37,97.16 305.44,45.09 309.25,45.09 D08.K2 | v354.33,217.17 362.58,208.91 368.3,208.91 369.57,207.65 369.57,207.01 382.27,194.31 385.44,194.31 B02.E2 | v337.82,211.46 337.19,211.46 v329.56,219.08
BRK_REQ1  (via drill 0.61)
  Top 0.152: v131.44,163.83 131.44,165.1 v133.35,167 | v254,149.22 247.65,149.22 243.21,144.78 241.3,144.78 v237.49,140.97 | v375.29,194.31 375.29,193.68 368.3,186.69 368.3,186.06 358.14,175.9 358.14,174.62 v357.5,173.99 | v325.12,192.41 324.49,192.41 312.42,180.34 v312.42,179.71
  Route2 0.152: v155.57,144.15 174.62,144.15 175.9,145.41 175.9,151.77 192.41,168.28 | 192.41,168.28 200.66,176.53 203.84,176.53 204.47,177.16 B16.L2 | v249.56,50.8 246.38,47.62 246.38,45.09 D13.K2 | v184.15,121.29 184.15,123.19 182.88,124.46 196.85,138.43 196.85,140.97 200.66,144.78 201.29,144.78 206.38,149.86 206.38,154.31 192.41,168.28 | v254,149.22 255.91,151.13 257.18,151.13 294.64,188.59 295.91,188.59 297.18,189.87 297.18,193.04 B09.E2
  Route15 0.152: v357.5,173.99 349.25,182.25 347.98,182.25 346.07,184.15 346.07,184.78 345.44,185.42 339.73,185.42 339.09,186.06 333.38,186.06 329.56,189.87 328.93,189.87 326.39,192.41 v325.12,192.41
  Bottom 0.152: v131.44,163.83 127,163.83 116.2,174.62 116.2,177.16 B23.L2 | v133.35,167 134.62,168.28 149.86,153.03 149.86,149.86 v155.57,144.15 | v249.56,50.8 231.78,68.58 231.78,74.3 184.78,121.29 v184.15,121.29 | v237.49,140.97 237.49,142.24 215.26,164.47 215.26,165.1 214,166.37 213.36,166.37 206.38,173.36 206.38,175.9 205.1,177.16 B16.L2 | v375.29,194.31 381.63,187.96 385.44,187.96 B02.H2 | v312.42,179.71 312.42,180.34 307.34,185.42 302.26,185.42 297.81,189.87 297.81,192.41 297.18,193.04 B09.E2
BRK_REQ2  (via drill 0.61)
  Top 0.152: v137.79,185.42 140.34,185.42 143.51,188.59 148.59,188.59 155.57,195.58 155.57,196.85 v156.84,198.12 | v191.13,175.26 191.13,176.53 191.77,177.16 B17.L2 | v201.93,60.96 186.06,45.09 182.88,45.09 D18.K2 | v186.69,75.57 186.69,76.84 v214.63,104.78 215.26,104.78 219.07,108.59 219.07,116.21 225.43,122.56 225.43,123.19 227.33,125.09 227.97,125.09 231.14,128.27 231.14,128.91 233.04,130.81 233.68,130.81 250.19,147.32 v250.19,147.96 | v191.77,138.43 191.77,142.88 203.84,154.94 203.84,156.84 202.56,158.12 v203.2,158.75 | v384.18,183.52 384.18,182.88 374.01,172.72 373.38,172.72 368.3,167.64 368.3,167 343.54,142.24 v342.9,142.24 | v334.01,149.86 330.2,149.86 323.85,143.51 315.6,143.51 307.34,135.25 v303.53,135.25 | v291.46,147.96 285.12,147.96 282.57,145.41 280.67,145.41 266.7,131.44 v264.8,131.44
  Route2 0.152: v250.19,147.96 254,151.77 254,153.03 258.44,157.48 258.44,159.39 261.62,162.56 262.89,162.56 283.21,182.88 283.21,184.15 284.48,185.42 285.12,185.42 289.56,189.87 293.37,189.87 B09.F2 | v384.18,183.52 384.18,182.88 385.44,181.61 B02.K2
  Route15 0.152: v137.79,185.42 137.16,185.42 128.91,193.68 128.91,196.22 B22.D2 | v201.93,60.96 201.29,60.96 v186.69,75.57 | v342.9,142.24 341.63,142.24 v334.01,149.86
  Bottom 0.152: v156.84,198.12 156.84,197.49 162.56,191.77 168.91,191.77 175.26,185.42 180.34,185.42 180.97,184.78 180.97,180.34 184.15,177.16 184.15,176.53 187.96,172.72 | 187.96,172.72 189.87,172.72 191.77,174.62 v191.13,175.26 | v214.63,104.78 193.68,125.73 193.68,131.44 193.04,132.08 193.04,133.35 190.5,135.89 190.5,137.16 v191.77,138.43 | v203.2,158.75 201.93,158.75 187.96,172.72 | v303.53,135.25 303.53,135.89 v291.46,147.96 | v264.8,131.44 263.52,131.44 262.89,132.08 257.81,132.08 257.18,132.72 257.18,135.89 260.99,139.7 259.71,140.97 257.18,140.97 v250.19,147.96
BRK_REQ3  (via drill 0.61)
  Top 0.152: v113.03,60.96 137.16,85.09 137.16,85.73 138.43,87 139.06,87 191.13,139.06 191.13,147.96 v196.85,153.67 | v175.9,176.53 178.44,176.53 179.07,177.16 B18.L2 | v292.1,184.15 292.1,184.78 294,186.69 296.55,186.69 B09.H2
  Route2 0.152: v337.82,214.63 332.74,214.63 319.4,201.3 319.4,200.66 313.69,194.94 307.34,194.94 300.99,188.59 297.81,188.59 297.18,187.96 B09.H2 | v133.99,194.94 133.35,194.31 132.08,194.31 B22.E2 | v268.61,201.3 268.61,200.66 260.35,192.41 260.35,191.14 254,184.78 254,182.25 255.27,180.97 237.49,163.19 232.41,163.19 226.69,157.48 226.06,157.48 221.62,153.03 221.62,151.13 v213.36,142.88
  Route15 0.152: v113.03,60.96 117.47,56.52 117.47,50.16 118.75,48.89 118.75,45.09 D23.K2 | v196.85,153.67 196.85,156.21 193.04,160.02 193.04,161.29 186.69,167.64 186.69,169.55 188.59,171.45 184.15,175.9 180.97,175.9 179.71,177.16 B18.L2 | v292.1,184.15 290.83,184.15 279.4,195.58 279.4,196.22 278.13,197.49 276.86,197.49 275.59,198.75 270.51,198.75 268.61,200.66 v268.61,201.3
  Bottom 0.152: v337.82,214.63 341.63,210.82 342.9,210.82 346.07,207.65 349.25,207.65 354.96,201.93 356.24,201.93 356.87,201.3 361.31,201.3 361.95,200.66 361.95,200.03 363.22,198.75 364.49,198.75 385.44,177.8 385.44,175.26 B02.M2 | v133.99,194.94 137.16,191.77 143.51,191.77 162.56,172.72 170.81,172.72 175.26,177.16 v175.9,176.53 | v213.36,142.88 207.65,142.88 204.47,146.05 202.56,146.05 198.12,150.5 197.49,150.5 196.22,151.77 196.22,153.03 v196.85,153.67
BRK_REQ4  (via drill 0.61)
  Top 0.152: v345.44,150.5 345.44,149.86 344.81,149.22 344.81,147.32 334.64,137.16 v335.92,135.89 | v53.98,53.98 53.98,57.78 55.88,59.69 55.88,60.96 120.65,125.73 120.65,129.54 119.38,130.81 138.43,149.86 138.43,152.4 151.13,165.1 | 156.84,170.81 162.56,176.53 165.74,176.53 166.37,177.16 B19.L2 | 151.13,165.1 156.84,170.81 | v147.96,167 149.22,167 151.13,165.1 | v297.81,178.44 265.43,146.05 265.43,145.41 v262.89,142.88 | v240.03,153.67 240.03,153.03 237.49,150.5 235.59,150.5 v226.69,141.61 | v217.17,147.96 210.19,147.96 204.47,142.24 203.2,142.24 v202.56,141.61 | v158.75,168.28 158.75,168.91 156.84,170.81
  Route2 0.152: v363.22,139.7 363.86,140.34 363.86,142.24 367.67,146.05 367.67,147.32 384.18,163.83 384.18,165.74 385.44,167 385.44,167.64 B02.P2
  Route15 0.152: v335.92,135.89 331.47,140.34 331.47,140.97 327.02,145.41 327.02,147.96 323.21,151.77 323.21,154.31 324.49,155.58 320.04,160.02 314.96,160.02 297.81,177.16 v297.81,178.44
  Bottom 0.152: v363.22,139.7 360.68,137.16 355.6,142.24 352.43,142.24 345.44,149.22 v345.44,150.5 | v297.81,178.44 297.81,179.71 299.08,180.97 295.27,184.78 294,184.78 B09.J2 | v53.98,53.98 53.98,50.16 55.24,48.89 55.24,45.09 D28.K2 | v147.96,167 146.05,168.91 146.05,169.55 135.89,179.71 135.25,179.71 132.08,182.88 132.08,186.69 B22.H2 | v262.89,142.88 256.54,142.88 250.19,149.22 248.92,149.22 244.47,153.67 v240.03,153.67 | v226.69,141.61 223.52,141.61 v217.17,147.96 | v202.56,141.61 200.03,141.61 196.85,144.78 196.22,144.78 186.69,154.31 183.51,154.31 179.71,150.5 177.8,150.5 161.29,167 160.02,167 v158.75,168.28
BRK_REQ5  (via drill 0.61)
  Top 0.152: 133.99,192.41 128.91,187.33 128.91,184.78 B22.J2 | 133.99,192.41 136.53,192.41 139.06,189.87 v139.7,190.5 | v147.32,205.11 146.69,205.11 133.99,192.41 | v373.38,171.45 v342.9,140.97 | v171.45,138.43 173.99,138.43 176.53,135.89 185.42,144.78 186.69,144.78 196.85,154.94 198.12,154.94 203.2,160.02 v207.65,160.02
  Route2 0.152: v155.57,155.58 154.94,154.94 145.41,164.47 145.41,165.74 153.67,173.99 153.67,177.16 B20.L2 | v225.43,142.88 231.78,142.88 232.41,143.51 233.04,143.51 236.22,140.34 235.59,139.7 236.85,138.43 237.49,138.43 242.57,133.35 238.12,128.91 238.12,127.64 237.49,127 237.49,125.73 244.47,118.75 245.11,119.38 248.28,119.38 248.92,120.02 249.56,120.02 255.27,114.3 276.23,135.25 277.5,135.25 291.46,149.22 300.36,149.22 306.07,154.94 306.07,155.58 314.32,163.83 315.6,163.83 v316.87,165.1
  Route15 0.152: v316.87,165.1 315.6,165.1 299.72,180.97 297.18,180.97 B09.K2
  Bottom 0.152: v139.7,190.5 139.7,189.23 149.86,179.07 153.03,179.07 153.67,178.44 B20.L2 | v147.32,205.11 143.51,205.11 130.18,218.44 130.18,223.52 106.68,247.02 106.68,250.19 A24.K2 | v373.38,171.45 382.27,162.56 385.44,162.56 B02.S2 | v342.9,140.97 342.26,141.61 341,141.61 335.28,147.32 334.01,147.32 316.87,164.47 v316.87,165.1 | v155.57,155.58 154.94,154.94 156.21,153.67 156.21,150.5 168.28,138.43 v171.45,138.43 | v207.65,160.02 207.65,159.39 218.44,148.59 218.44,147.96 219.71,146.69 221.62,146.69 v225.43,142.88
BRK_REQ6  (via drill 0.61)
  Top 0.152: v332.74,120.02 332.74,121.29 340.36,128.91 345.44,128.91 346.07,129.54 346.07,134.62 346.71,135.25 346.71,136.53 353.69,143.51 357.5,143.51 365.76,151.77 365.76,153.67 363.86,155.58 368.3,160.02 368.3,161.29 368.94,161.93 368.94,163.19 367.67,164.47 v368.3,165.1 | B21.L2 140.97,177.8 139.7,176.53 136.53,179.71 132.72,179.71 131.44,178.44 128.91,178.44 B22.L2 128.27,177.16 127.64,176.53 127.64,173.99 123.19,169.55 117.47,169.55 109.22,161.29 v109.22,160.66 | v216.53,149.22 205.74,149.22 205.1,148.59 201.93,148.59 v193.04,139.7
  Route2 0.152: B09.L2 294,177.16 294,173.99 297.18,170.81 295.27,168.91 v295.27,164.47 297.81,164.47 300.36,161.93 295.91,157.48 295.91,156.84 287.02,147.96 277.5,147.96 269.88,140.34 269.88,135.25 260.35,125.73 254,125.73 250.19,121.92 248.28,121.92 240.66,129.54 v240.03,129.54 | v163.83,153.67 162.56,153.67 160.02,156.21 158.12,154.31 154.94,154.31 140.97,168.28 142.88,170.18 142.88,175.9 141.6,177.16 B21.L2
  Route15 0.152: v295.27,164.47 295.27,160.02 302.26,153.03 302.26,150.5 v332.74,120.02 | v240.03,129.54 225.43,144.15 222.25,144.15 217.17,149.22 v216.53,149.22
  Bottom 0.152: v368.3,165.1 368.3,164.47 374.65,158.12 374.65,157.48 378.46,153.67 384.18,153.67 385.44,154.94 B02.U2 | v109.22,160.66 104.78,160.66 77.47,187.96 79.38,189.87 79.38,203.84 76.2,207.01 76.2,207.65 43.18,240.66 44.45,241.94 44.45,245.11 43.18,246.38 43.18,250.19 A29.K2 | v193.04,139.7 191.77,139.7 189.87,141.61 180.97,141.61 173.99,148.59 170.81,148.59 168.91,150.5 166.37,150.5 163.83,153.03 v163.83,153.67
BRK_SYNC_CLK  (via drill 0.61)
  Top 0.152: v347.98,41.27 332.11,25.4 332.11,22.86 D06.T2 | v311.79,205.11 310.51,205.11 307.34,201.93 301.62,201.93 300.99,201.3 294.64,201.3 285.75,192.41 285.75,191.14 282.57,187.96 282.57,183.52 v281.31,182.25
  Route2 0.152: v311.79,205.11 327.02,220.34 327.02,220.98 331.47,225.43 331.47,227.97 A06.T2 | v281.31,182.25 281.31,181.61 262.89,163.19 256.54,163.19 250.19,156.84 247.01,156.84 246.38,156.21 B13.U2
  Route15 0.152: v274.32,121.92 276.23,121.92 278.13,123.83 262.89,139.06 262.89,141.61 250.19,154.31 247.01,154.31 246.38,154.94 B13.U2
  Bottom 0.152: v347.98,41.27 333.38,55.88 333.38,62.23 326.39,69.22 326.39,70.48 314.32,82.55 312.42,82.55 299.08,95.89 298.45,95.89 292.1,102.23 292.1,102.87 276.23,118.75 276.23,120.02 v274.32,121.92
BRK_SYNC_CLK\  (via drill 0.61)
  Top 0.152: v108.58,231.78 108.58,230.5 101.6,223.52 v101.6,222.25 | v174.62,141.61 177.8,141.61 200.66,164.47 201.93,164.47 v203.2,165.74 | v215.26,157.48 219.07,157.48 234.95,173.36 v236.22,173.36
  Route15 0.152: v149.86,171.45 149.86,170.18 147.96,168.28 v174.62,141.61 | v236.22,173.36 237.49,173.36 244.47,166.37 244.47,160.66 243.21,159.39 B13.T2
  Bottom 0.152: v108.58,231.78 101.6,238.76 101.6,240.66 100.33,241.94 99.69,241.94 92.08,249.56 92.08,261.62 64.77,288.92 13.34,288.92 PDP-12/8I/8.1 | v101.6,222.25 101.6,214.63 124.46,191.77 130.18,191.77 146.05,175.9 146.05,175.26 147.96,173.36 148.59,173.36 149.86,172.09 v149.86,171.45 | v203.2,165.74 205.1,167.64 v215.26,157.48
BT1B  (via drill 0.61)
  Top 0.152: v154.31,290.83 140.97,290.83 137.79,287.65 9.53,287.65 8.26,288.92 PDP-12/8I/8.5 | v240.03,260.35 240.66,260.35 247.65,267.33 247.65,267.97 248.28,268.6 250.19,268.6 252.73,266.06 260.35,273.69 260.35,274.32 264.16,278.13 274.95,278.13 278.13,281.3 285.12,281.3 285.75,281.94 316.23,281.94 v317.5,283.21 | v142.88,146.05 144.15,146.05 155.57,157.48 155.57,163.19 162.56,170.18 163.83,170.18 165.1,171.45 165.1,172.09 170.18,177.16 v170.81,177.16
  Route2 0.152: v142.88,111.12 142.88,116.21 147.32,120.65 141.6,126.37 v144.15,128.91 | v170.81,177.16 170.81,179.07 180.97,189.23 180.97,202.56 184.15,205.74 184.15,209.55 193.68,219.08 198.12,219.08 216.53,237.49 216.53,238.12 217.81,239.4 219.07,239.4 228.6,248.92 234.31,248.92 241.94,256.54 241.94,258.44 v240.03,260.35
  Route15 0.152: v154.31,290.83 182.25,290.83 194.31,278.76 196.22,278.76 213.36,261.62 222.25,261.62 230.5,269.88 v240.03,260.35 | v275.59,12.07 267.97,12.07 266.7,13.34 248.28,13.34 237.49,24.13 231.14,24.13 199.39,55.88 193.68,55.88 184.15,65.41 182.88,65.41 181.61,66.67 181.61,68.58 180.97,69.22 180.97,71.75 178.44,74.3 178.44,76.2 167.64,87 162.56,87 142.88,106.68 v142.88,111.12
  Bottom 0.152: v317.5,283.21 337.19,283.21 384.18,236.22 384.18,233.68 385.44,232.41 A02.S2 | v275.59,12.07 276.23,11.43 299.08,11.43 300.99,13.34 335.28,13.34 335.92,12.7 349.25,12.7 360.68,1.27 370.2,1.27 387.35,18.41 387.35,19.69 386.08,20.95 386.08,24.77 D02.S2 | v144.15,128.91 144.15,131.44 142.88,132.72 142.88,135.89 147.96,140.97 v142.88,146.05
CYC_SEL  (via drill 0.61)
  Top 0.152: v219.07,167.64 217.81,166.37 217.81,165.74 B15.R2 | v273.05,257.18 273.05,256.54 272.42,255.91 267.33,255.91 259.71,248.28 258.44,248.28 v254.63,244.47
  Route2 0.152: v190.5,194.94 190.5,199.39 196.85,205.74 196.85,209.55 200.03,212.72 200.03,216.53 v201.93,218.44 | v273.05,257.18 273.69,257.18 274.32,257.81 280.67,251.46 283.85,251.46 A10.K2 | v254.63,244.47 254.63,243.84 199.39,188.59 v198.12,188.59
  Bottom 0.152: v219.07,167.64 214,172.72 213.36,172.72 204.47,181.61 204.47,182.25 203.2,183.52 201.93,183.52 197.49,187.96 | 197.49,187.96 v190.5,194.94 | v201.93,218.44 198.12,218.44 193.04,223.52 187.96,223.52 168.28,243.21 168.28,245.75 167,247.02 A19.L2 | v198.12,188.59 197.49,187.96
CYC_SEL0  (via drill 0.61)
  Top 0.152: v276.86,92.08 276.86,91.44 269.88,84.46 268.61,84.46 v267.97,83.82 | v296.55,55.24 296.55,53.98 288.29,45.72 285.12,45.72 284.48,45.09 D10.K2
  Bottom 0.152: v276.86,92.08 276.86,92.71 262.89,106.68 262.25,106.68 257.81,111.12 257.81,111.76 246.38,123.19 243.21,123.19 C13.F2 | v267.97,83.82 267.97,83.19 295.91,55.24 v296.55,55.24
CYC_SEL1  (via drill 0.61)
  Top 0.152: v229.24,95.25 231.78,97.79 231.78,100.33 227.33,104.78 238.76,116.21 241.94,116.21 242.57,116.84 C13.J2
  Route2 0.152: v240.66,78.11 234.95,72.39 234.95,69.22 232.41,66.67 232.41,65.41 217.81,50.8 220.34,48.26 220.34,45.09 D15.K2
  Route15 0.152: v240.66,78.11 240.66,83.82 238.12,86.36 238.12,87 232.41,92.71 231.78,92.71 v229.24,95.25
CYC_SEL2  (via drill 0.61)
  Top 0.152: v176.53,81.28 170.81,75.57 170.81,74.3 161.29,64.77 160.02,64.77 158.75,63.5 158.75,62.87 157.48,61.59 157.48,60.32 162.56,55.24 162.56,53.98 161.93,53.34 161.93,52.07 158.12,48.26 158.12,46.35 157.48,45.72 157.48,45.09 D20.K2 | v185.42,87.63 185.42,88.27 200.66,103.51 205.74,103.51 v211.46,109.22
  Route2 0.152: v176.53,81.28 177.8,81.28 184.15,87.63 v185.42,87.63 | v211.46,109.22 212.09,109.22 215.26,112.4 219.71,112.4 230.5,101.6 238.76,109.86 241.94,109.86 242.57,110.49 C13.L2
CYC_SEL3  (via drill 0.61)
  Top 0.152: v224.16,90.17 225.43,90.17 238.76,103.51 241.94,103.51 242.57,104.14 C13.N2
  Route2 0.152: v224.16,90.17 216.53,82.55 209.55,82.55 198.12,71.12 193.68,71.12 187.32,64.77 180.97,64.77 158.75,42.55 153.03,42.55 151.13,40.64 142.88,48.89 140.34,48.89 137.79,46.35 136.53,46.35 130.18,40.01 124.46,40.01 118.11,33.66 111.12,33.66 109.22,31.75 97.16,43.81 93.98,43.81 D25.K2
CYC_SEL4  (via drill 0.61)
